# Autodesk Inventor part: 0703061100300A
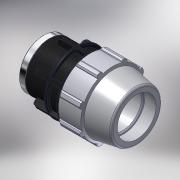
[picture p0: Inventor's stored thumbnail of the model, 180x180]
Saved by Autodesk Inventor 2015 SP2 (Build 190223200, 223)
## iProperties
Created: 2017-02
Part Number: 0703061100300A
Material: PVC-Piping
Description: PLASSON FEMALE ADAPTOR 110-3"
Document SubType Name: Modeling
Designer: KIM
Mass: 92.6774 g
Surface Area: 199.44 cm^2
Volume: 66.1981 cm^3
Density: 1.4 g/cm^3
Appearance: PTFE
Author: KIM
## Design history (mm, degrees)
derived "87030.ipt"
feature "Solid1::87030.ipt"
tag "TaggingFeature1"
body "Solid1"
other parameters: "d4" = 37.28571, "d5" = 65.25, "d7" = 181, "d9" = 37.28571, "d11" = 7.45714, "d12" = 144.8, "d13" = 120 deg, "d14" = 143, "d15" = 8 deg, "d16" = 162.9, "d18" = 5.5, "d19" = 35 deg, "d20" = 17.5 deg, "d21" = 168.33, "d23" = 0, "d25" = 360 deg, "d27" = 3.62, "d34" = 9.05, "d35" = 78.3, "d36" = 0, "d42" = 65.25, "d43" = 5.43, "d46" = 3.3, "d49" = 213, "d51" = 261, "d53" = 2.2, "d55" = 360 deg, "d62" = 88, "d63" = 84.926, "d64" = 87, "d65" = 9.05, "d69" = 130.32, "d70" = 4.525, "d71" = 12, "d72" = 0.5, "d73" = 1, "E_" = 181, "H_" = 261, "l_" = 213, "Rp_Rc_" = 84.926
